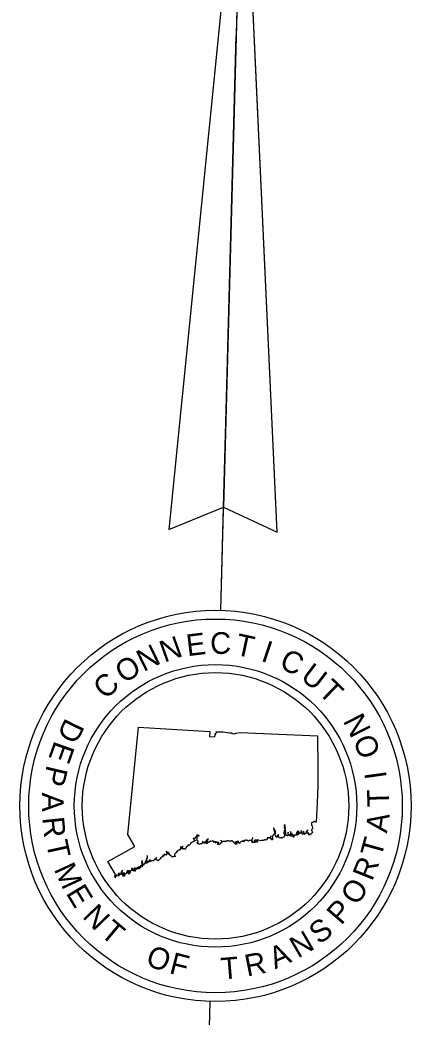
# Model space of a CAD drawing. Extents: x 0 to 2603, y -226 to 830.
# Drawn here: x 26.02 to 41.99, y 643.33 to 684.04 of the extents above; entities that cross this region are included whole.
import ezdxf

# ---------------------------------------------------------------- set-up
doc = ezdxf.new("R2010")
doc.units = 0
doc.layers.add('CT_TSH_Map_Arrow', color=7, linetype='Continuous')

msp = doc.modelspace()

# ---------------------------------------------------------------- linework, layer by layer
at = {"layer": 'CT_TSH_Map_Arrow'}
for p, q in [((35.129, 693.474), (32.096, 663.242)), ((34.336, 664.153), (35.129, 693.474)), ((36.524, 663.122), (35.129, 693.474)), ((34.222, 659.939), (34.856, 683.398)), ((32.096, 663.242), (34.336, 664.153)), ((34.222, 659.937), (34.336, 664.153)), ((34.336, 664.153), (36.524, 663.122)), ((33.727, 641.614), (33.791, 643.969))]:
    msp.add_line(p, q, dxfattribs=at)
msp.add_lwpolyline([(34.336, 664.153), (36.524, 663.122), (35.129, 693.474), (35.129, 693.474)], close=True, dxfattribs=at)
for points in [[(29.917, 649.158), (29.614, 649.688), (30.714, 650.301), (30.432, 650.79), (30.866, 655.16), (33.781, 654.991), (33.76, 654.766), (33.977, 654.791), (33.982, 654.819), (34.003, 654.827), (33.994, 654.848), (34.012, 654.871), (34.001, 654.875), (34, 654.886), (33.994, 654.887), (33.986, 654.886), (33.987, 654.891), (33.991, 654.896), (33.988, 654.898), (33.988, 654.903), (33.994, 654.9), (33.995, 654.895), (34.008, 654.903), (34.019, 654.893), (34.036, 654.916), (34.047, 654.946), (34.041, 654.958), (34.022, 654.966), (34.031, 654.982), (34.301, 654.978), (34.583, 654.939), (34.668, 654.934), (34.673, 654.901), (34.78, 654.895), (34.821, 654.927), (35.008, 654.945), (38.168, 654.815), (38.18, 653.524), (38.189, 652.794), (38.16, 652.065), (38.12, 651.29), (38.114, 651.288), (38.104, 651.29), (38.096, 651.297), (38.081, 651.294), (38.076, 651.298), (38.062, 651.308), (38.044, 651.312), (38.026, 651.311), (38.012, 651.302), (38.003, 651.287), (37.964, 651.268), (37.953, 651.27), (37.939, 651.272), (37.925, 651.259), (37.925, 651.25), (37.922, 651.228), (37.929, 651.222), (37.932, 651.2), (37.928, 651.19), (37.924, 651.177), (37.93, 651.168), (37.942, 651.145), (37.953, 651.143), (37.953, 651.143), (37.961, 651.133), (37.965, 651.118), (37.96, 651.099), (37.973, 651.079), (37.973, 651.074), (37.964, 651.063), (37.964, 651.056), (37.968, 651.042), (37.966, 651.025), (37.954, 651.016), (37.94, 651.001), (37.938, 650.979), (37.933, 650.969), (37.934, 650.952), (37.945, 650.931), (37.941, 650.925), (37.948, 650.914), (37.954, 650.921), (37.967, 650.91), (37.958, 650.899), (37.971, 650.886), (37.965, 650.866), (37.93, 650.82), (37.911, 650.811), (37.907, 650.801), (37.884, 650.796), (37.868, 650.774), (37.852, 650.768), (37.852, 650.76), (37.844, 650.752), (37.836, 650.756), (37.834, 650.774), (37.829, 650.792), (37.825, 650.783), (37.817, 650.783), (37.821, 650.791)], [(36.407, 650.969), (36.41, 650.976), (36.406, 651.015), (36.392, 651.046), (36.38, 651.044), (36.398, 650.978), (36.398, 650.932), (36.403, 650.899), (36.41, 650.901), (36.419, 650.861), (36.423, 650.827), (36.409, 650.801), (36.422, 650.785), (36.397, 650.786), (36.365, 650.767), (36.367, 650.756), (36.344, 650.743), (36.337, 650.721), (36.34, 650.71), (36.337, 650.687), (36.33, 650.669), (36.332, 650.642), (36.339, 650.606), (36.336, 650.584), (36.328, 650.564), (36.315, 650.561), (36.299, 650.564), (36.294, 650.58), (36.293, 650.597), (36.277, 650.609), (36.262, 650.61), (36.263, 650.627), (36.275, 650.625), (36.273, 650.619), (36.285, 650.616), (36.272, 650.697), (36.268, 650.695), (36.273, 650.731), (36.266, 650.722), (36.258, 650.703), (36.258, 650.691), (36.264, 650.689), (36.252, 650.666), (36.229, 650.642), (36.214, 650.642), (36.213, 650.623), (36.206, 650.643), (36.193, 650.654), (36.174, 650.655), (36.158, 650.651), (36.145, 650.64), (36.139, 650.651), (36.121, 650.646), (36.127, 650.615), (36.122, 650.595), (36.119, 650.602), (36.108, 650.591), (36.108, 650.586), (36.101, 650.572), (36.089, 650.568), (36.073, 650.55), (36.052, 650.563), (36.035, 650.565), (36.008, 650.562), (35.992, 650.556), (35.979, 650.547), (35.948, 650.541), (35.93, 650.541), (35.91, 650.533), (35.906, 650.539), (35.878, 650.538), (35.853, 650.528), (35.786, 650.534), (35.777, 650.551), (35.695, 650.549), (35.679, 650.555), (35.671, 650.557), (35.661, 650.547), (35.655, 650.547), (35.643, 650.556), (35.631, 650.555), (35.625, 650.549), (35.617, 650.556), (35.608, 650.555), (35.589, 650.527), (35.59, 650.502), (35.603, 650.498), (35.61, 650.503), (35.616, 650.503), (35.624, 650.506), (35.63, 650.5), (35.64, 650.499), (35.644, 650.508), (35.654, 650.516), (35.666, 650.516), (35.686, 650.512), (35.699, 650.522), (35.7, 650.525), (35.703, 650.526), (35.708, 650.522), (35.71, 650.504)], [(37.252, 650.753), (37.229, 650.737), (37.217, 650.776), (37.209, 650.736), (37.207, 650.673), (37.177, 650.67), (37.181, 650.696), (37.146, 650.72), (37.172, 650.739), (37.168, 650.747), (37.148, 650.793), (37.136, 650.793), (37.136, 650.825), (37.128, 650.825), (37.127, 650.778), (37.135, 650.751), (37.106, 650.73), (37.092, 650.703), (37.062, 650.724), (37.04, 650.747), (37.079, 650.803), (37.087, 650.825), (37.082, 650.864), (37.064, 650.905), (37.07, 650.861), (37.068, 650.813), (37.021, 650.757), (36.995, 650.764), (36.993, 650.79), (36.976, 650.818), (36.968, 650.88), (36.964, 650.817), (36.98, 650.797), (36.984, 650.758), (36.956, 650.748), (36.96, 650.728), (36.935, 650.73), (36.932, 650.753), (36.89, 650.748), (36.895, 650.759), (36.877, 650.829), (36.882, 650.838), (36.869, 650.874), (36.874, 650.921), (36.857, 650.966), (36.868, 651.023), (36.849, 651.091), (36.85, 651.125), (36.839, 651.193), (36.807, 651.149), (36.805, 651.075), (36.819, 651.02), (36.841, 651.003), (36.827, 650.951), (36.806, 650.93), (36.809, 650.902), (36.822, 650.902), (36.821, 650.889), (36.787, 650.852), (36.838, 650.771), (36.833, 650.733), (36.81, 650.722), (36.812, 650.694), (36.777, 650.661), (36.757, 650.659), (36.733, 650.635), (36.71, 650.647), (36.665, 650.648), (36.638, 650.639), (36.598, 650.659), (36.574, 650.69), (36.584, 650.777), (36.576, 650.791), (36.572, 650.752), (36.558, 650.739), (36.545, 650.75), (36.538, 650.741), (36.545, 650.734), (36.542, 650.726), (36.524, 650.725), (36.522, 650.712), (36.513, 650.712), (36.508, 650.698), (36.519, 650.68), (36.501, 650.671), (36.477, 650.704), (36.467, 650.701), (36.475, 650.726), (36.462, 650.748), (36.448, 650.765), (36.463, 650.846), (36.466, 650.88), (36.459, 650.893), (36.451, 650.924), (36.451, 650.941), (36.458, 650.965), (36.442, 650.948), (36.432, 650.923), (36.411, 650.922), (36.417, 650.936), (36.407, 650.969)], [(37.821, 650.791), (37.817, 650.798), (37.813, 650.798), (37.807, 650.785), (37.797, 650.789), (37.813, 650.813), (37.83, 650.814), (37.826, 650.823), (37.804, 650.823), (37.791, 650.829), (37.794, 650.839), (37.806, 650.843), (37.804, 650.846), (37.777, 650.843), (37.773, 650.832), (37.762, 650.832), (37.753, 650.846), (37.756, 650.851), (37.748, 650.887), (37.747, 650.915), (37.762, 650.958), (37.769, 650.971), (37.761, 650.966), (37.74, 650.922), (37.722, 650.912), (37.709, 650.915), (37.716, 650.909), (37.724, 650.909), (37.737, 650.917), (37.741, 650.908), (37.735, 650.871), (37.705, 650.854), (37.696, 650.83), (37.685, 650.825), (37.664, 650.825), (37.646, 650.81), (37.649, 650.793), (37.64, 650.784), (37.632, 650.802), (37.631, 650.813), (37.62, 650.826), (37.631, 650.847), (37.62, 650.865), (37.628, 650.868), (37.628, 650.878), (37.609, 650.887), (37.606, 650.908), (37.578, 650.891), (37.576, 650.873), (37.599, 650.872), (37.594, 650.86), (37.592, 650.809), (37.574, 650.791), (37.56, 650.802), (37.559, 650.822), (37.536, 650.819), (37.532, 650.835), (37.52, 650.828), (37.513, 650.849), (37.513, 650.881), (37.512, 650.944), (37.504, 650.936), (37.498, 650.851), (37.45, 650.823), (37.436, 650.817), (37.431, 650.823), (37.442, 650.851), (37.436, 650.867), (37.416, 650.845), (37.393, 650.857), (37.387, 650.794), (37.382, 650.78), (37.358, 650.754), (37.36, 650.797), (37.329, 650.792), (37.35, 650.868), (37.373, 650.864), (37.387, 650.865), (37.392, 650.876), (37.405, 650.866), (37.41, 650.872), (37.408, 650.91), (37.398, 650.918), (37.395, 650.903), (37.378, 650.894), (37.374, 650.899), (37.384, 650.915), (37.361, 650.915), (37.338, 650.9), (37.343, 650.884), (37.336, 650.872), (37.323, 650.883), (37.312, 650.843), (37.322, 650.835), (37.318, 650.82), (37.299, 650.812), (37.3, 650.778), (37.279, 650.728), (37.27, 650.728), (37.262, 650.772), (37.252, 650.753)], [(33.278, 650.463), (33.292, 650.465), (33.303, 650.475), (33.302, 650.495), (33.293, 650.511), (33.253, 650.553), (33.263, 650.577), (33.264, 650.591), (33.253, 650.629), (33.263, 650.704), (33.279, 650.721), (33.284, 650.718), (33.31, 650.732), (33.325, 650.732), (33.34, 650.773), (33.337, 650.776), (33.319, 650.74), (33.278, 650.729), (33.262, 650.734), (33.259, 650.778), (33.254, 650.777), (33.258, 650.717), (33.225, 650.705), (33.209, 650.694), (33.167, 650.639), (33.165, 650.623), (33.147, 650.61), (33.135, 650.624), (33.113, 650.62), (33.106, 650.635), (33.118, 650.571), (33.144, 650.544), (33.143, 650.534), (33.188, 650.555), (33.187, 650.546), (33.149, 650.53), (33.122, 650.492), (33.031, 650.461), (33.028, 650.448), (33.006, 650.456), (33.001, 650.435), (32.98, 650.42), (32.967, 650.374), (32.941, 650.345), (32.929, 650.343), (32.896, 650.361), (32.866, 650.293), (32.845, 650.285), (32.819, 650.289), (32.796, 650.219), (32.767, 650.183), (32.74, 650.184), (32.735, 650.2), (32.678, 650.198), (32.661, 650.172), (32.633, 650.221), (32.686, 650.297), (32.677, 650.301), (32.624, 650.234), (32.595, 650.254), (32.586, 650.289), (32.581, 650.248), (32.612, 650.233), (32.614, 650.22), (32.574, 650.216), (32.535, 650.148), (32.516, 650.151), (32.459, 650.119), (32.379, 650.023), (32.337, 649.978), (32.338, 649.92), (32.376, 649.903), (32.358, 649.884), (32.35, 649.891), (32.306, 649.89), (32.244, 649.864), (32.126, 649.952), (32.102, 649.965), (32.121, 649.983), (32.108, 649.982), (32.103, 649.998), (32.124, 650.026), (32.116, 650.029), (32.098, 650.008), (32.098, 649.982), (32.069, 649.993), (32.04, 650.02), (32.074, 650.09), (32.072, 650.096), (32.048, 650.055), (32.042, 650.04), (32.03, 650.035), (32.019, 650.037), (32.014, 650.046), (32.012, 650.084), (32.004, 650.09), (31.992, 650.101), (31.997, 650.085), (32.006, 650.083), (32.006, 650.053), (32.012, 650.025)], [(33.753, 650.475), (33.747, 650.481), (33.737, 650.482), (33.714, 650.467), (33.701, 650.466), (33.689, 650.461), (33.682, 650.44), (33.66, 650.42), (33.657, 650.421), (33.663, 650.431), (33.66, 650.432), (33.64, 650.424), (33.631, 650.414), (33.629, 650.426), (33.637, 650.438), (33.618, 650.455), (33.607, 650.456), (33.624, 650.478), (33.642, 650.484), (33.649, 650.469), (33.664, 650.471), (33.678, 650.489), (33.675, 650.499), (33.666, 650.511), (33.652, 650.514), (33.637, 650.527), (33.644, 650.545), (33.658, 650.552), (33.671, 650.567), (33.686, 650.568), (33.694, 650.564), (33.698, 650.562), (33.707, 650.574), (33.708, 650.575), (33.7, 650.586), (33.707, 650.595), (33.702, 650.607), (33.704, 650.612), (33.7, 650.611), (33.698, 650.608), (33.703, 650.595), (33.697, 650.587), (33.702, 650.576), (33.695, 650.569), (33.684, 650.578), (33.667, 650.574), (33.654, 650.556), (33.64, 650.549), (33.631, 650.526), (33.646, 650.512), (33.663, 650.508), (33.662, 650.501), (33.631, 650.501), (33.626, 650.484), (33.606, 650.496), (33.605, 650.506), (33.601, 650.501), (33.598, 650.503), (33.593, 650.511), (33.588, 650.504), (33.577, 650.457), (33.567, 650.453), (33.57, 650.442), (33.56, 650.422), (33.552, 650.418), (33.546, 650.436), (33.551, 650.438), (33.555, 650.451), (33.549, 650.441), (33.539, 650.434), (33.535, 650.445), (33.542, 650.461), (33.532, 650.466), (33.533, 650.479), (33.517, 650.474), (33.517, 650.467), (33.493, 650.465), (33.489, 650.443), (33.471, 650.445), (33.486, 650.471), (33.49, 650.503), (33.477, 650.513), (33.475, 650.508), (33.485, 650.503), (33.484, 650.482), (33.466, 650.455), (33.445, 650.404), (33.394, 650.399), (33.362, 650.39), (33.361, 650.386), (33.357, 650.386), (33.353, 650.391), (33.33, 650.401), (33.316, 650.398), (33.303, 650.385), (33.296, 650.387), (33.294, 650.398), (33.272, 650.412), (33.253, 650.424), (33.262, 650.452), (33.278, 650.463)], [(34.23, 650.447), (34.223, 650.456), (34.22, 650.454), (34.22, 650.442), (34.216, 650.417), (34.193, 650.389), (34.191, 650.393), (34.184, 650.395), (34.18, 650.384), (34.171, 650.379), (34.163, 650.385), (34.131, 650.375), (34.104, 650.378), (34.104, 650.386), (34.121, 650.386), (34.129, 650.384), (34.132, 650.388), (34.12, 650.388), (34.118, 650.396), (34.128, 650.397), (34.128, 650.402), (34.096, 650.394), (34.088, 650.4), (34.091, 650.405), (34.102, 650.417), (34.111, 650.419), (34.119, 650.428), (34.13, 650.433), (34.139, 650.447), (34.132, 650.456), (34.134, 650.461), (34.125, 650.468), (34.107, 650.456), (34.1, 650.456), (34.081, 650.448), (34.08, 650.452), (34.07, 650.447), (34.068, 650.449), (34.074, 650.458), (34.084, 650.459), (34.086, 650.469), (34.084, 650.472), (34.088, 650.478), (34.078, 650.487), (34.044, 650.46), (34.046, 650.468), (34.051, 650.47), (34.051, 650.477), (34.041, 650.472), (34.037, 650.479), (34.035, 650.475), (34.039, 650.459), (34.031, 650.453), (34.028, 650.466), (34.019, 650.465), (34.014, 650.455), (34.017, 650.449), (34.011, 650.442), (34.002, 650.441), (34.01, 650.451), (33.993, 650.451), (33.988, 650.459), (34.005, 650.468), (34.005, 650.471), (33.993, 650.467), (33.995, 650.48), (33.991, 650.479), (33.986, 650.483), (33.984, 650.502), (33.98, 650.517), (33.981, 650.484), (33.926, 650.465), (33.935, 650.473), (33.932, 650.473), (33.932, 650.481), (33.939, 650.486), (33.936, 650.489), (33.929, 650.486), (33.925, 650.502), (33.925, 650.514), (33.917, 650.514), (33.915, 650.527), (33.907, 650.53), (33.899, 650.543), (33.899, 650.539), (33.903, 650.527), (33.903, 650.517), (33.897, 650.512), (33.888, 650.511), (33.884, 650.52), (33.872, 650.52), (33.859, 650.504), (33.848, 650.511), (33.839, 650.512), (33.833, 650.496), (33.809, 650.509), (33.786, 650.51), (33.767, 650.502), (33.77, 650.495), (33.756, 650.474), (33.753, 650.475)], [(35.098, 650.508), (35.091, 650.506), (35.078, 650.498), (35.036, 650.483), (35.021, 650.471), (34.996, 650.441), (34.997, 650.429), (34.986, 650.423), (34.968, 650.436), (34.958, 650.438), (34.948, 650.433), (34.94, 650.502), (34.936, 650.507), (34.932, 650.51), (34.929, 650.528), (34.922, 650.509), (34.928, 650.502), (34.876, 650.498), (34.851, 650.478), (34.834, 650.468), (34.827, 650.47), (34.828, 650.496), (34.822, 650.48), (34.82, 650.47), (34.829, 650.454), (34.837, 650.449), (34.86, 650.453), (34.879, 650.469), (34.887, 650.476), (34.9, 650.478), (34.909, 650.485), (34.918, 650.49), (34.922, 650.488), (34.922, 650.482), (34.916, 650.476), (34.909, 650.477), (34.899, 650.473), (34.89, 650.465), (34.882, 650.466), (34.869, 650.439), (34.868, 650.402), (34.858, 650.391), (34.845, 650.39), (34.841, 650.384), (34.831, 650.382), (34.824, 650.392), (34.761, 650.461), (34.718, 650.501), (34.683, 650.52), (34.658, 650.522), (34.659, 650.518), (34.643, 650.517), (34.64, 650.515), (34.638, 650.511), (34.615, 650.512), (34.602, 650.507), (34.591, 650.509), (34.582, 650.517), (34.57, 650.52), (34.56, 650.517), (34.561, 650.513), (34.552, 650.514), (34.551, 650.517), (34.526, 650.527), (34.518, 650.529), (34.513, 650.526), (34.502, 650.527), (34.497, 650.525), (34.496, 650.527), (34.478, 650.524), (34.478, 650.52), (34.466, 650.52), (34.457, 650.516), (34.454, 650.51), (34.437, 650.501), (34.424, 650.504), (34.424, 650.499), (34.411, 650.502), (34.372, 650.492), (34.37, 650.497), (34.356, 650.496), (34.355, 650.493), (34.292, 650.499), (34.289, 650.496), (34.286, 650.499), (34.275, 650.506), (34.267, 650.5), (34.241, 650.523), (34.238, 650.533), (34.224, 650.547), (34.223, 650.545), (34.233, 650.534), (34.237, 650.523), (34.268, 650.492), (34.266, 650.487), (34.258, 650.488), (34.248, 650.468), (34.252, 650.465), (34.254, 650.451), (34.251, 650.434), (34.23, 650.447)], [(35.71, 650.504), (35.721, 650.5), (35.722, 650.491), (35.72, 650.487), (35.719, 650.478), (35.714, 650.477), (35.707, 650.483), (35.698, 650.487), (35.688, 650.486), (35.673, 650.483), (35.653, 650.482), (35.631, 650.47), (35.614, 650.457), (35.6, 650.453), (35.586, 650.457), (35.574, 650.46), (35.559, 650.46), (35.537, 650.452), (35.523, 650.44), (35.516, 650.439), (35.515, 650.456), (35.49, 650.501), (35.492, 650.506), (35.502, 650.504), (35.503, 650.495), (35.514, 650.498), (35.516, 650.505), (35.517, 650.513), (35.515, 650.518), (35.511, 650.515), (35.507, 650.524), (35.507, 650.535), (35.498, 650.532), (35.492, 650.54), (35.486, 650.538), (35.496, 650.554), (35.494, 650.555), (35.494, 650.562), (35.498, 650.565), (35.499, 650.58), (35.506, 650.588), (35.506, 650.596), (35.516, 650.61), (35.522, 650.611), (35.528, 650.64), (35.523, 650.643), (35.523, 650.65), (35.528, 650.663), (35.521, 650.655), (35.517, 650.643), (35.521, 650.625), (35.511, 650.613), (35.503, 650.599), (35.502, 650.598), (35.501, 650.589), (35.493, 650.582), (35.493, 650.568), (35.488, 650.563), (35.491, 650.552), (35.481, 650.54), (35.468, 650.542), (35.461, 650.536), (35.455, 650.542), (35.448, 650.543), (35.442, 650.533), (35.416, 650.545), (35.4, 650.546), (35.378, 650.534), (35.366, 650.52), (35.353, 650.519), (35.333, 650.531), (35.33, 650.538), (35.321, 650.542), (35.301, 650.546), (35.291, 650.546), (35.278, 650.55), (35.259, 650.552), (35.235, 650.549), (35.218, 650.541), (35.18, 650.512), (35.175, 650.498), (35.17, 650.495), (35.161, 650.497), (35.156, 650.505), (35.16, 650.506), (35.168, 650.53), (35.178, 650.533), (35.181, 650.54), (35.169, 650.551), (35.175, 650.54), (35.163, 650.533), (35.161, 650.521), (35.151, 650.505), (35.14, 650.514), (35.131, 650.533), (35.129, 650.52), (35.139, 650.504), (35.151, 650.501), (35.137, 650.497), (35.127, 650.503), (35.098, 650.508)], [(31.035, 649.609), (31.021, 649.628), (31.02, 649.614), (31.005, 649.612), (30.989, 649.645), (30.994, 649.655), (31.014, 649.669), (31.009, 649.691), (31.02, 649.704), (31.011, 649.729), (30.997, 649.692), (31.005, 649.672), (30.982, 649.658), (30.997, 649.604), (31.002, 649.554), (30.995, 649.545), (30.984, 649.525), (31, 649.523), (31.002, 649.543), (31.013, 649.544), (31.016, 649.491), (31.011, 649.47), (30.994, 649.468), (30.986, 649.498), (30.977, 649.489), (30.977, 649.51), (30.966, 649.497), (30.954, 649.526), (30.955, 649.494), (30.94, 649.473), (30.944, 649.464), (30.917, 649.426), (30.916, 649.465), (30.906, 649.458), (30.899, 649.423), (30.877, 649.413), (30.883, 649.407), (30.897, 649.41), (30.896, 649.382), (30.875, 649.383), (30.845, 649.396), (30.844, 649.42), (30.856, 649.46), (30.846, 649.473), (30.85, 649.456), (30.838, 649.432), (30.839, 649.393), (30.778, 649.362), (30.775, 649.375), (30.821, 649.43), (30.783, 649.4), (30.767, 649.399), (30.758, 649.418), (30.715, 649.381), (30.75, 649.38), (30.743, 649.355), (30.73, 649.353), (30.727, 649.359), (30.715, 649.362), (30.717, 649.342), (30.706, 649.35), (30.711, 649.322), (30.727, 649.345), (30.737, 649.341), (30.699, 649.275), (30.675, 649.326), (30.691, 649.376), (30.705, 649.397), (30.717, 649.439), (30.675, 649.37), (30.674, 649.336), (30.665, 649.323), (30.648, 649.32), (30.662, 649.311), (30.648, 649.3), (30.633, 649.35), (30.622, 649.351), (30.637, 649.366), (30.641, 649.351), (30.653, 649.366), (30.58, 649.41), (30.591, 649.359), (30.619, 649.34), (30.603, 649.333), (30.602, 649.317), (30.593, 649.307), (30.594, 649.339), (30.589, 649.34), (30.567, 649.286), (30.533, 649.295), (30.512, 649.291), (30.505, 649.311), (30.507, 649.249), (30.527, 649.241), (30.498, 649.184), (30.477, 649.181), (30.47, 649.169), (30.467, 649.241), (30.449, 649.261), (30.478, 649.304), (30.469, 649.335)], [(32.012, 650.025), (32.034, 649.988), (32.011, 649.98), (32.008, 649.958), (31.994, 649.945), (31.986, 649.953), (31.946, 649.948), (31.902, 649.922), (31.869, 649.883), (31.869, 649.914), (31.904, 649.944), (31.923, 649.977), (31.941, 649.989), (31.923, 649.986), (31.881, 649.941), (31.869, 649.95), (31.856, 649.93), (31.865, 649.931), (31.864, 649.918), (31.836, 649.902), (31.841, 649.887), (31.818, 649.855), (31.787, 649.86), (31.761, 649.818), (31.753, 649.772), (31.708, 649.756), (31.662, 649.713), (31.625, 649.731), (31.612, 649.731), (31.599, 649.739), (31.593, 649.763), (31.565, 649.773), (31.611, 649.846), (31.562, 649.787), (31.535, 649.767), (31.531, 649.774), (31.501, 649.763), (31.501, 649.734), (31.453, 649.706), (31.443, 649.715), (31.409, 649.712), (31.361, 649.681), (31.335, 649.693), (31.32, 649.692), (31.307, 649.7), (31.312, 649.715), (31.323, 649.715), (31.352, 649.742), (31.325, 649.755), (31.293, 649.724), (31.297, 649.707), (31.295, 649.688), (31.292, 649.674), (31.269, 649.66), (31.26, 649.634), (31.244, 649.656), (31.25, 649.664), (31.234, 649.661), (31.217, 649.665), (31.242, 649.671), (31.25, 649.691), (31.225, 649.681), (31.217, 649.679), (31.215, 649.67), (31.181, 649.678), (31.205, 649.757), (31.195, 649.763), (31.207, 649.812), (31.213, 649.813), (31.231, 649.822), (31.236, 649.843), (31.227, 649.848), (31.225, 649.898), (31.211, 649.915), (31.208, 649.911), (31.219, 649.895), (31.215, 649.89), (31.221, 649.85), (31.214, 649.823), (31.21, 649.823), (31.198, 649.805), (31.187, 649.77), (31.193, 649.739), (31.177, 649.706), (31.173, 649.722), (31.139, 649.66), (31.188, 649.624), (31.19, 649.632), (31.202, 649.626), (31.189, 649.599), (31.122, 649.636), (31.109, 649.587), (31.083, 649.564), (31.084, 649.552), (31.072, 649.53), (31.055, 649.535), (31.041, 649.559), (31.048, 649.573), (31.045, 649.589), (31.035, 649.591), (31.035, 649.609)], [(30.469, 649.335), (30.467, 649.307), (30.437, 649.274), (30.436, 649.257), (30.422, 649.262), (30.407, 649.319), (30.399, 649.32), (30.414, 649.244), (30.392, 649.206), (30.386, 649.206), (30.38, 649.223), (30.39, 649.236), (30.382, 649.254), (30.378, 649.226), (30.345, 649.173), (30.326, 649.174), (30.297, 649.14), (30.287, 649.087), (30.224, 649.085), (30.225, 649.11), (30.236, 649.123), (30.265, 649.101), (30.307, 649.171), (30.274, 649.232), (30.213, 649.147), (30.188, 649.146), (30.18, 649.182), (30.205, 649.184), (30.206, 649.213), (30.188, 649.208), (30.19, 649.259), (30.215, 649.319), (30.211, 649.324), (30.16, 649.25), (30.152, 649.246), (30.152, 649.205), (30.162, 649.189), (30.128, 649.167), (30.127, 649.155), (30.118, 649.155), (30.097, 649.138), (30.089, 649.149), (30.099, 649.156), (30.108, 649.195), (30.09, 649.19), (30.088, 649.157), (30.078, 649.149), (30.069, 649.192), (30.06, 649.152), (30.059, 649.196), (30.038, 649.191), (30.053, 649.176), (30.053, 649.164), (30.04, 649.17), (30.037, 649.177), (30.029, 649.167), (30.053, 649.146), (30.053, 649.125), (30.033, 649.09), (30.021, 649.108), (30.014, 649.109), (30.002, 649.093), (29.991, 649.1), (29.982, 649.126), (29.974, 649.128), (29.982, 649.153), (29.967, 649.133), (29.954, 649.086), (29.943, 649.08), (29.932, 649.069), (29.9, 649.015), (29.893, 649.019), (29.905, 649.034), (29.897, 649.053), (29.893, 649.089), (29.916, 649.148), (29.917, 649.158)]]:
    msp.add_lwpolyline(points, dxfattribs=at)
for radius in [7.987, 7.628, 5.768, 5.44]:
    msp.add_circle((34.007, 651.953), radius, dxfattribs=at)

# ---------------------------------------------------------------- texts
for s, rotation, p in [('E', 6.9036, (32.864, 658.061)), ('C', 0.5519, (33.793, 658.153)), ('N', 19.607, (31.918, 657.793)), ('T', 347.8485, (34.772, 658.132)), ('I', 341.4968, (35.83, 657.883)), ('N', 25.9587, (31.063, 657.417)), ('C', 335.1451, (36.566, 657.602)), ('O', 32.3104, (30.268, 656.926)), ('U', 322.4417, (37.434, 657.14)), ('C', 45.0138, (29.543, 656.26)), ('T', 316.09, (38.16, 656.563)), ('D', 244.0689, (27.888, 655.577)), ('N', 117.035, (40.377, 655.063)), ('E', 250.4206, (27.442, 654.645)), ('O', 110.6833, (40.769, 654.108)), ('P', 256.7723, (27.124, 653.648)), ('I', 97.9799, (41.003, 653.102)), ('A', 269.4757, (26.924, 652.5)), ('T', 91.6282, (41.098, 651.921)), ('R', 275.8274, (26.932, 651.467)), ('A', 80.9714, (41.004, 650.82)), ('T', 282.179, (27.08, 650.453)), ('T', 74.6197, (40.768, 649.808)), ('M', 294.8824, (27.393, 649.367)), ('R', 68.2681, (40.4, 648.85)), ('O', 55.5647, (39.783, 647.844)), ('E', 301.2341, (27.877, 648.393)), ('P', 49.213, (39.141, 647.054)), ('N', 313.9375, (28.537, 647.414)), ('T', 320.2892, (29.258, 646.684)), ('S', 36.5096, (38.243, 646.27)), ('N', 30.1579, (37.374, 645.712)), ('O', 339.3443, (31.108, 645.471)), ('A', 23.8062, (36.438, 645.279)), ('F', 345.696, (32.082, 645.129)), ('T', 4.7511, (34.263, 644.862)), ('R', 11.1028, (35.295, 644.983))]:
    msp.add_text(s, height=0.886, rotation=rotation, dxfattribs=at).set_placement(p)

doc.saveas('drawing.dxf')
